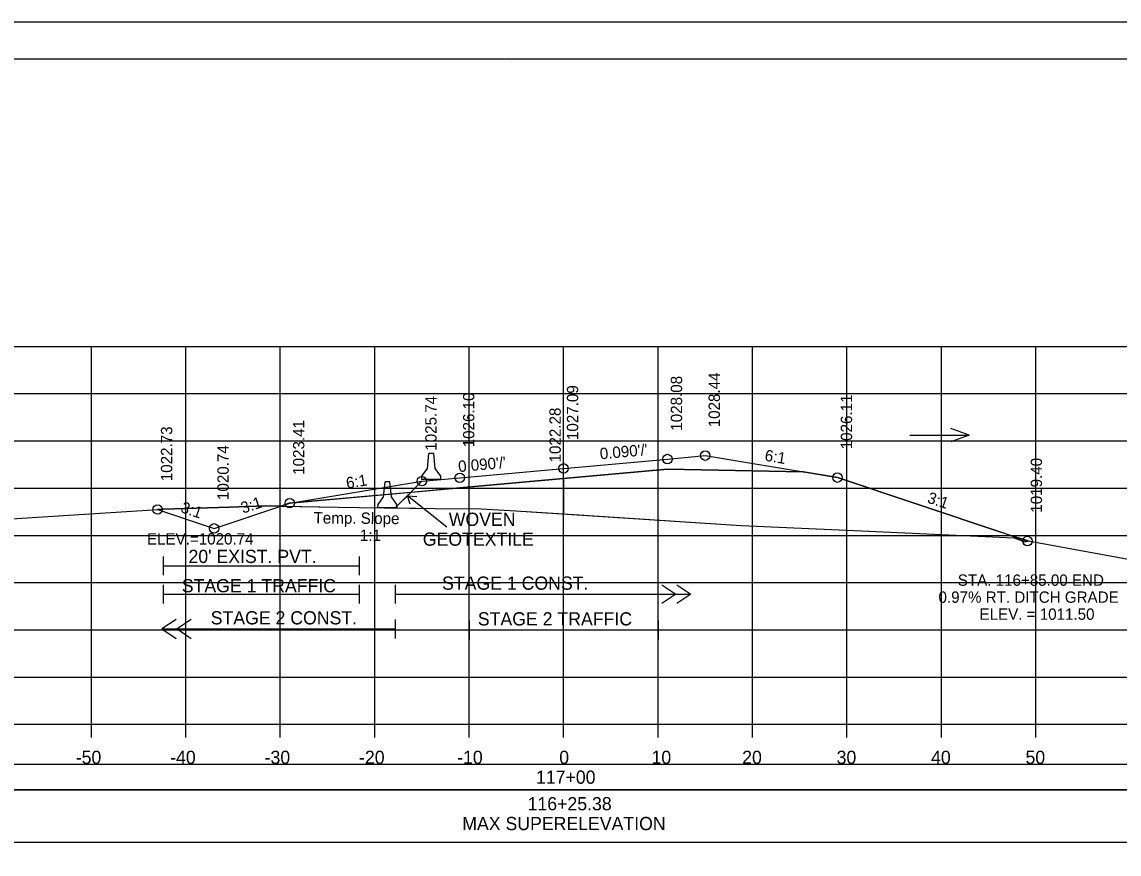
# Model space of a CAD drawing. Extents: x 1370565 to 1374448, y 301010 to 304637.
# Drawn here: x 1370677.7 to 1370793.8, y 302842.4 to 302930.5 of the extents above; entities that cross this region are included whole.
import ezdxf

# ---------------------------------------------------------------- set-up
doc = ezdxf.new("R2010")
doc.units = 0
for name, color, linetype in [('R_Alt Surface', 7, 'Continuous'), ('R_Axis', 7, 'Continuous'), ('R_Axis Annot', 7, 'Continuous'), ('R_Border', 7, 'Continuous'), ('R_Contours', 7, 'Continuous'), ('R_Drive', 7, 'Continuous'), ('R_Exist Surface', 7, 'Continuous'), ('R_Fin Surface', 7, 'Continuous'), ('R_Grid', 7, 'Continuous'), ('R_MOT', 7, 'Continuous'), ('R_No Plot', 7, 'Continuous'), ('R_Water', 7, 'Continuous'), ('R_Water Annot', 7, 'Continuous'), ('R_Xsect Elev', 7, 'Continuous'), ('R_Xsect Slope', 7, 'Continuous')]:
    doc.layers.add(name, color=color, linetype=linetype)

# ---------------------------------------------------------------- blocks, each defined once
blk = doc.blocks.new('MEDBAR_P')
at = {"layer": 'R_MOT'}
for p, q in [((-2.46, -0.98), (-1.63, 6.93)), ((-0.38, 6.93), (-1.63, 6.93)), ((0.87, 6.93), (-0.38, 6.93)), ((1.71, -0.98), (0.87, 6.93)), ((-5.37, -6.81), (-5.34, -5.15)), ((-5.34, -5.15), (-2.46, -0.98)), ((4.66, -5.15), (1.71, -0.98)), ((4.63, -6.81), (4.66, -5.15)), ((4.63, -6.81), (-5.37, -6.81))]:
    blk.add_line(p, q, dxfattribs=at)

msp = doc.modelspace()

# ---------------------------------------------------------------- linework, layer by layer
at = {"layer": 'R_Alt Surface'}
for points in [[(1370705.98, 302879.57), (1370724.03, 302881.2), (1370735.03, 302882.19), (1370746.03, 302883.18), (1370760.41, 302882.89)], [(1370722.68, 302877.03), (1370718.5, 302880.38)], [(1370718.79, 302879.49), (1370718.5, 302880.38), (1370719.49, 302880.3)], [(1370692.63, 302873.95), (1370692.63, 302871.95)], [(1370713.37, 302873.95), (1370713.37, 302871.95)], [(1370692.63, 302872.95), (1370713.37, 302872.95)], [(1370692.63, 302870.95), (1370692.63, 302868.95)], [(1370713.37, 302870.95), (1370713.37, 302868.95)], [(1370717.19, 302870.95), (1370717.19, 302868.95)], [(1370745.42, 302870.95), (1370746.92, 302869.95), (1370745.42, 302868.95)], [(1370747.02, 302870.95), (1370748.52, 302869.95), (1370747.02, 302868.95)], [(1370692.63, 302869.95), (1370713.37, 302869.95)], [(1370717.19, 302869.95), (1370748.52, 302869.95)], [(1370694, 302867.27), (1370692.5, 302866.27), (1370694, 302865.27)], [(1370695.6, 302867.27), (1370694.1, 302866.27), (1370695.6, 302865.27)], [(1370717.19, 302867.27), (1370717.19, 302865.27)], [(1370692.5, 302866.27), (1370717.19, 302866.27)], [(1370725.03, 302867.16), (1370725.03, 302865.16)], [(1370725.03, 302866.16), (1370745.03, 302866.16)], [(1370745.03, 302867.16), (1370745.03, 302865.16)]]:
    msp.add_lwpolyline(points, dxfattribs=at)
at = {"layer": 'R_Axis'}
for p, q in [((1370585.03, 302856.18), (1370885.03, 302856.18)), ((1370685.03, 302854.78), (1370685.03, 302856.18)), ((1370695.03, 302854.78), (1370695.03, 302856.18)), ((1370705.03, 302854.78), (1370705.03, 302856.18)), ((1370715.03, 302854.78), (1370715.03, 302856.18)), ((1370725.03, 302854.78), (1370725.03, 302856.18)), ((1370735.03, 302854.78), (1370735.03, 302856.18)), ((1370745.03, 302854.78), (1370745.03, 302856.18)), ((1370755.03, 302854.78), (1370755.03, 302856.18)), ((1370765.03, 302854.78), (1370765.03, 302856.18)), ((1370775.03, 302854.78), (1370775.03, 302856.18)), ((1370785.03, 302854.78), (1370785.03, 302856.18))]:
    msp.add_line(p, q, dxfattribs=at)
for points in [[(1370692.63, 302873.95), (1370692.63, 302871.95)], [(1370713.37, 302873.95), (1370713.37, 302871.95)], [(1370692.63, 302872.95), (1370713.37, 302872.95)], [(1370692.63, 302870.95), (1370692.63, 302868.95)], [(1370713.37, 302870.95), (1370713.37, 302868.95)], [(1370692.63, 302869.95), (1370713.37, 302869.95)]]:
    msp.add_lwpolyline(points, dxfattribs=at)
at = {"layer": 'R_Border'}
for p, q in [((1370577.03, 302926.64), (1370893.21, 302926.64)), ((1370729.55, 302926.38), (1370729.55, 302926.38)), ((1370729.55, 302926.38), (1370729.55, 302926.38))]:
    msp.add_line(p, q, dxfattribs=at)
at = {"layer": 'R_Contours'}
for p, q in [((1370735.03, 302882.19), (1370735.03, 302878.46)), ((1370735.03, 302878.46), (1370735.03, 302882.19)), ((1370717.19, 302879.08), (1370718.84, 302880.73)), ((1370718.84, 302880.73), (1370717.38, 302879.27)), ((1370705.08, 302879.27), (1370703.46, 302879.29)), ((1370705.98, 302879.57), (1370705.08, 302879.27)), ((1370717.38, 302879.27), (1370717.37, 302879.11))]:
    msp.add_line(p, q, dxfattribs=at)
for points in [[(1370760.41, 302882.89), (1370746.03, 302883.18), (1370735.03, 302882.19)], [(1370784.22, 302875.61), (1370782.26, 302876.21), (1370781.42, 302876.49), (1370764.03, 302882.29), (1370760.41, 302882.89)], [(1370735.03, 302882.19), (1370724.03, 302881.2), (1370718.84, 302880.73)], [(1370718.84, 302880.73), (1370715.98, 302880.47), (1370705.98, 302879.57)], [(1370703.46, 302879.29), (1370699.65, 302879.17), (1370692.63, 302878.95), (1370692.04, 302878.91)], [(1370692.04, 302878.91), (1370698.02, 302876.92), (1370705.08, 302879.27)], [(1370705.08, 302879.27), (1370711.16, 302879.18), (1370713.37, 302879.13), (1370717.19, 302879.08)], [(1370717.37, 302879.11), (1370717.37, 302879.08)], [(1370717.37, 302879.08), (1370721.38, 302879.03), (1370726.3, 302878.97), (1370729.96, 302878.79), (1370735.03, 302878.46)], [(1370735.03, 302878.46), (1370753.83, 302877.24), (1370765.8, 302876.69), (1370782.74, 302875.91), (1370783.86, 302875.5), (1370784.01, 302875.54), (1370784.22, 302875.61)]]:
    msp.add_lwpolyline(points, dxfattribs=at)
at = {"layer": 'R_Drive'}
for points in [[(1370585.82, 302849.22), (1370884.24, 302849.22), (1370884.24, 302851.92), (1370585.82, 302851.92)], [(1370585.82, 302843.7), (1370884.24, 302843.7), (1370884.24, 302849.22), (1370585.82, 302849.22)]]:
    msp.add_lwpolyline(points, close=True, dxfattribs=at)
at = {"layer": 'R_Exist Surface'}
msp.add_lwpolyline([(1370659.74, 302876.82), (1370678.76, 302878.08), (1370692.63, 302878.95), (1370699.65, 302879.17), (1370703.46, 302879.29), (1370711.16, 302879.18), (1370713.37, 302879.13), (1370721.38, 302879.03), (1370726.3, 302878.97), (1370729.96, 302878.79), (1370753.83, 302877.24), (1370765.8, 302876.69), (1370782.74, 302875.91), (1370783.86, 302875.5), (1370784.01, 302875.54), (1370784.22, 302875.61), (1370801.76, 302872.4)], dxfattribs=at)
at = {"layer": 'R_Fin Surface'}
msp.add_line((1370720.03, 302881.92), (1370717.19, 302879.08), dxfattribs=at)
msp.add_lwpolyline([(1370692.04, 302878.91), (1370698.02, 302876.92), (1370706.03, 302879.59), (1370720.03, 302881.92), (1370724.03, 302882.28), (1370735.03, 302883.27), (1370746.03, 302884.26), (1370750.03, 302884.62), (1370764.03, 302882.29), (1370781.42, 302876.49), (1370781.49, 302876.47), (1370782.26, 302876.21), (1370782.34, 302876.18), (1370784.14, 302875.58)], dxfattribs=at)
at = {"layer": 'R_Grid'}
for p, q in [((1370585.03, 302896.18), (1370885.03, 302896.18)), ((1370685.03, 302856.18), (1370685.03, 302896.18)), ((1370695.03, 302856.18), (1370695.03, 302896.18)), ((1370705.03, 302856.18), (1370705.03, 302896.18)), ((1370715.03, 302856.18), (1370715.03, 302896.18)), ((1370725.03, 302856.18), (1370725.03, 302896.18)), ((1370735.03, 302856.18), (1370735.03, 302896.18)), ((1370745.03, 302856.18), (1370745.03, 302896.18)), ((1370755.03, 302856.18), (1370755.03, 302896.18)), ((1370765.03, 302856.18), (1370765.03, 302896.18)), ((1370775.03, 302856.18), (1370775.03, 302896.18)), ((1370785.03, 302856.18), (1370785.03, 302896.18)), ((1370585.03, 302891.18), (1370885.03, 302891.18)), ((1370585.03, 302886.18), (1370885.03, 302886.18)), ((1370585.03, 302881.18), (1370885.03, 302881.18)), ((1370585.03, 302876.18), (1370885.03, 302876.18)), ((1370585.03, 302871.18), (1370885.03, 302871.18)), ((1370585.03, 302866.18), (1370885.03, 302866.18)), ((1370585.03, 302861.18), (1370885.03, 302861.18)), ((1370585.03, 302856.18), (1370885.03, 302856.18))]:
    msp.add_line(p, q, dxfattribs=at)
at = {"layer": 'R_No Plot'}
msp.add_line((1370564.63, 302930.53), (1370897.96, 302930.53), dxfattribs=at)
for points in [[(1370564.62, 302930.53), (1370897.96, 302930.53), (1370897.96, 302717.2), (1370564.62, 302717.2)], [(1370810.95, 302926.64), (1370830.57, 302926.64), (1370830.57, 302916.76), (1370846.68, 302916.76), (1370869.88, 302916.76), (1370869.88, 302884.09), (1370893.09, 302884.09), (1370893.21, 302721.18), (1370577.03, 302721.18), (1370577.03, 302926.64)]]:
    msp.add_lwpolyline(points, close=True, dxfattribs=at)
for centre in [(1370746.03, 302884.26), (1370750.03, 302884.62), (1370735.03, 302883.27), (1370720.03, 302881.92), (1370724.03, 302882.28), (1370764.03, 302882.29), (1370706.03, 302879.59), (1370692.04, 302878.91), (1370698.02, 302876.92), (1370784.14, 302875.58)]:
    msp.add_circle(centre, 0.5, dxfattribs=at)
at = {"layer": 'R_Water Annot'}
for p, q in [((1370777.97, 302886.78), (1370776.04, 302887.48)), ((1370771.68, 302886.78), (1370777.97, 302886.78)), ((1370777.97, 302886.78), (1370776.04, 302886.08))]:
    msp.add_line(p, q, dxfattribs=at)
at = {"layer": 'R_Xsect Elev'}
msp.add_line((1370735.03, 302878.46), (1370735.03, 302890.34), dxfattribs=at)

# ---------------------------------------------------------------- block references
at = {"layer": 'R_Fin Surface', "xscale": 0.2, "yscale": 0.20000000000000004}
for p in [(1370721.1, 302883.46), (1370716.45, 302880.47)]:
    msp.add_blockref('MEDBAR_P', p, dxfattribs=at)

# ---------------------------------------------------------------- texts
at = {"layer": 'R_Axis Annot'}
for s, p in [('WOVEN ', (1370722.87, 302877.18)), ('GEOTEXTILE', (1370720.12, 302875.08)), ("20' EXIST. PVT.", (1370695.31, 302873.25)), ('-50', (1370683.37, 302851.98)), ('-40', (1370693.37, 302851.98)), ('-30', (1370703.37, 302851.98)), ('-20', (1370713.37, 302851.98)), ('-10', (1370723.76, 302851.98)), ('0', (1370734.57, 302851.98)), ('10', (1370744.34, 302851.98)), ('20', (1370753.94, 302851.98)), ('30', (1370763.94, 302851.98)), ('40', (1370773.94, 302851.98)), ('50', (1370783.94, 302851.98)), ('117+00', (1370732.11, 302849.88)), ('116+25.38', (1370731.22, 302847.07)), ('MAX SUPERELEVATION', (1370724.3, 302844.97))]:
    msp.add_text(s, height=1.4, dxfattribs=at).set_placement(p)
at = {"layer": 'R_Water'}
for s, p in [('STAGE 1 TRAFFIC', (1370694.6, 302870.15)), ('STAGE 1 CONST.', (1370722.16, 302870.42)), ('STAGE 2 CONST.', (1370697.66, 302866.75)), ('STAGE 2 TRAFFIC', (1370725.95, 302866.64))]:
    msp.add_text(s, height=1.4, dxfattribs=at).set_placement(p)
at = {"layer": 'R_Xsect Elev'}
for s, p in [('1028.08', (1370747.58, 302887.26)), ('1028.44', (1370751.58, 302887.62)), ('1027.09', (1370736.58, 302886.27)), ('1025.74', (1370721.58, 302885.14)), ('1026.10', (1370725.58, 302885.5)), ('1026.11', (1370765.58, 302885.29)), ('1022.28', (1370734.73, 302883.9)), ('1023.41', (1370707.58, 302882.59)), ('1022.73', (1370693.59, 302881.91)), ('1020.74', (1370699.57, 302879.92)), ('1019.40', (1370785.69, 302878.58))]:
    msp.add_text(s, height=1.2, rotation=90, dxfattribs=at).set_placement(p)
for s, p in [('ELEV.=1020.74', (1370690.91, 302875.21)), ('STA. 116+85.00 END ', (1370776.77, 302870.84)), ('0.97% RT. DITCH GRADE', (1370774.73, 302869.04)), ('ELEV. = 1011.50', (1370779.07, 302867.24))]:
    msp.add_text(s, height=1.2, dxfattribs=at).set_placement(p)
at = {"layer": 'R_Xsect Slope'}
for s, rotation, p in [("0.090'/'", 5.1428, (1370738.92, 302884.22)), ('6:1', 350.5377, (1370756.26, 302884.09)), ("0.090'/'", 5.1428, (1370723.92, 302882.87)), ('6:1', 9.4623, (1370712.1, 302881.11)), ('3:1', 18.4349, (1370701.08, 302878.47)), ('3:1', 341.5651, (1370773.45, 302879.67)), ('3:1', 341.5668, (1370694.4, 302878.65)), ('Temp. Slope ', 359.538, (1370708.55, 302877.44)), ('1:1', 359.538, (1370713.46, 302875.6))]:
    msp.add_text(s, height=1.2, rotation=rotation, dxfattribs=at).set_placement(p)

doc.saveas('drawing.dxf')
